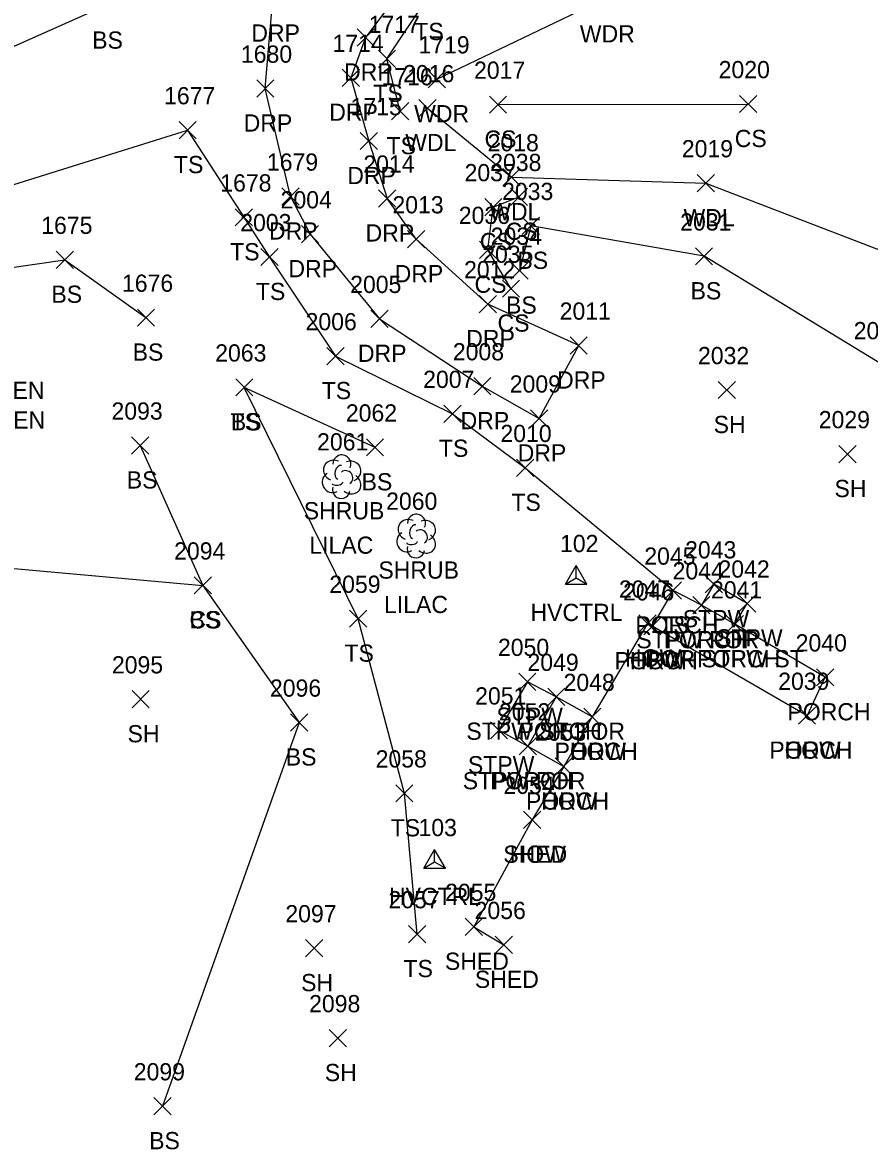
# Model space of a CAD drawing. Extents: x 1761340 to 1763889, y 696770 to 706023.
# Drawn here: x 1761761.6 to 1761860, y 700672.8 to 700803.7 of the extents above; entities that cross this region are included whole.
import ezdxf

# ---------------------------------------------------------------- set-up
doc = ezdxf.new("R2010")
doc.units = 0
for name, color, linetype in [('C_A', 7, 'Continuous'), ('C_I', 7, 'Continuous'), ('CPSM', 7, 'Continuous'), ('L_A', 7, 'Continuous'), ('L_C', 7, 'Continuous'), ('L_I', 7, 'Continuous'), ('L_TIC', 7, 'Continuous'), ('LAWA', 7, 'Continuous'), ('LBC', 7, 'Continuous'), ('LBF', 7, 'Continuous'), ('LELB', 7, 'Continuous'), ('LSH', 7, 'Continuous'), ('R_A', 7, 'Continuous'), ('R_I', 7, 'Continuous'), ('R_TIC', 7, 'Continuous'), ('RDP', 7, 'Continuous')]:
    doc.layers.add(name, color=color, linetype=linetype)

msp = doc.modelspace()

# ---------------------------------------------------------------- linework, layer by layer
at = {"layer": 'CPSM'}
for p, q in [((1761824.67, 700738.48), (1761825.92, 700740.65)), ((1761827.17, 700738.48), (1761825.92, 700740.65)), ((1761825.92, 700739.21), (1761825.92, 700740.65)), ((1761824.67, 700738.48), (1761825.92, 700739.21)), ((1761825.92, 700739.21), (1761825.92, 700739.21)), ((1761825.92, 700739.21), (1761827.17, 700738.48)), ((1761824.67, 700738.48), (1761827.17, 700738.48)), ((1761808.22, 700705.5), (1761809.47, 700707.66)), ((1761810.72, 700705.5), (1761809.47, 700707.66)), ((1761809.47, 700706.22), (1761809.47, 700707.66)), ((1761808.22, 700705.5), (1761809.47, 700706.22)), ((1761809.47, 700706.22), (1761809.47, 700706.22)), ((1761809.47, 700706.22), (1761810.72, 700705.5)), ((1761808.22, 700705.5), (1761810.72, 700705.5))]:
    msp.add_line(p, q, dxfattribs=at)
at = {"layer": 'L_TIC'}
for points in [[(1761802.94, 700798.51), (1761804.94, 700800.51)], [(1761804.94, 700798.51), (1761802.94, 700800.51)], [(1761808.72, 700796.14), (1761810.72, 700798.14)], [(1761810.72, 700796.14), (1761808.72, 700798.14)], [(1761815.83, 700793.19), (1761817.83, 700795.19)], [(1761817.83, 700793.19), (1761815.83, 700795.19)], [(1761844.9, 700793.26), (1761846.9, 700795.26)], [(1761846.9, 700793.26), (1761844.9, 700795.26)], [(1761804.48, 700792.43), (1761806.48, 700794.43)], [(1761806.48, 700792.43), (1761804.48, 700794.43)], [(1761807.64, 700792.79), (1761809.64, 700794.79)], [(1761809.64, 700792.79), (1761807.64, 700794.79)], [(1761779.78, 700790.23), (1761781.78, 700792.23)], [(1761781.78, 700790.23), (1761779.78, 700792.23)], [(1761817.4, 700784.77), (1761819.4, 700786.77)], [(1761819.4, 700784.77), (1761817.4, 700786.77)], [(1761839.97, 700784.07), (1761841.97, 700786.07)], [(1761841.97, 700784.07), (1761839.97, 700786.07)], [(1761818.27, 700782.48), (1761820.27, 700784.48)], [(1761820.27, 700782.48), (1761818.27, 700784.48)], [(1761815.29, 700781.29), (1761817.29, 700783.29)], [(1761817.29, 700781.29), (1761815.29, 700783.29)], [(1761786.31, 700780.1), (1761788.31, 700782.1)], [(1761788.31, 700780.1), (1761786.31, 700782.1)], [(1761819.65, 700779.11), (1761821.65, 700781.11)], [(1761821.65, 700779.11), (1761819.65, 700781.11)], [(1761814.67, 700776.33), (1761816.67, 700778.33)], [(1761816.67, 700776.33), (1761814.67, 700778.33)], [(1761765.51, 700775.17), (1761767.51, 700777.17)], [(1761767.51, 700775.17), (1761765.51, 700777.17)], [(1761789.3, 700775.49), (1761791.3, 700777.49)], [(1761791.3, 700775.49), (1761789.3, 700777.49)], [(1761839.77, 700775.57), (1761841.77, 700777.57)], [(1761841.77, 700775.57), (1761839.77, 700777.57)], [(1761818.33, 700773.91), (1761820.33, 700775.91)], [(1761820.33, 700773.91), (1761818.33, 700775.91)], [(1761817.34, 700771.82), (1761819.34, 700773.82)], [(1761819.34, 700771.82), (1761817.34, 700773.82)], [(1761774.94, 700768.45), (1761776.94, 700770.45)], [(1761776.94, 700768.45), (1761774.94, 700770.45)], [(1761796.95, 700763.98), (1761798.95, 700765.98)], [(1761798.95, 700763.98), (1761796.95, 700765.98)], [(1761786.36, 700760.35), (1761788.36, 700762.35)], [(1761788.36, 700760.35), (1761786.36, 700762.35)], [(1761786.36, 700760.35), (1761788.36, 700762.35)], [(1761788.36, 700760.35), (1761786.36, 700762.35)], [(1761842.41, 700760.04), (1761844.41, 700762.04)], [(1761844.41, 700760.04), (1761842.41, 700762.04)], [(1761810.56, 700757.28), (1761812.56, 700759.28)], [(1761812.56, 700757.28), (1761810.56, 700759.28)], [(1761774.27, 700753.6), (1761776.27, 700755.6)], [(1761776.27, 700753.6), (1761774.27, 700755.6)], [(1761801.55, 700753.38), (1761803.55, 700755.38)], [(1761803.55, 700753.38), (1761801.55, 700755.38)], [(1761856.44, 700752.6), (1761858.44, 700754.6)], [(1761858.44, 700752.6), (1761856.44, 700754.6)], [(1761818.98, 700751), (1761820.98, 700753)], [(1761820.98, 700751), (1761818.98, 700753)], [(1761781.55, 700737.35), (1761783.55, 700739.35)], [(1761783.55, 700737.35), (1761781.55, 700739.35)], [(1761781.55, 700737.35), (1761783.55, 700739.35)], [(1761783.55, 700737.35), (1761781.55, 700739.35)], [(1761836.17, 700736.75), (1761838.17, 700738.75)], [(1761838.17, 700736.75), (1761836.17, 700738.75)], [(1761836.17, 700736.75), (1761838.17, 700738.75)], [(1761838.17, 700736.75), (1761836.17, 700738.75)], [(1761840.91, 700737.48), (1761842.91, 700739.48)], [(1761842.91, 700737.48), (1761840.91, 700739.48)], [(1761839.46, 700735.04), (1761841.46, 700737.04)], [(1761841.46, 700735.04), (1761839.46, 700737.04)], [(1761839.46, 700735.04), (1761841.46, 700737.04)], [(1761841.46, 700735.04), (1761839.46, 700737.04)], [(1761844.79, 700735.25), (1761846.79, 700737.25)], [(1761846.79, 700735.25), (1761844.79, 700737.25)], [(1761799.59, 700733.48), (1761801.59, 700735.48)], [(1761801.59, 700733.48), (1761799.59, 700735.48)], [(1761833.21, 700732.92), (1761835.21, 700734.92)], [(1761835.21, 700732.92), (1761833.21, 700734.92)], [(1761843.35, 700732.83), (1761845.35, 700734.83)], [(1761845.35, 700732.83), (1761843.35, 700734.83)], [(1761843.35, 700732.83), (1761845.35, 700734.83)], [(1761845.35, 700732.83), (1761843.35, 700734.83)], [(1761833.76, 700732.6), (1761835.76, 700734.6)], [(1761835.76, 700732.6), (1761833.76, 700734.6)], [(1761833.76, 700732.6), (1761835.76, 700734.6)], [(1761835.76, 700732.6), (1761833.76, 700734.6)], [(1761819.25, 700726.15), (1761821.25, 700728.15)], [(1761821.25, 700726.15), (1761819.25, 700728.15)], [(1761853.84, 700726.67), (1761855.84, 700728.67)], [(1761855.84, 700726.67), (1761853.84, 700728.67)], [(1761774.32, 700724.12), (1761776.32, 700726.12)], [(1761776.32, 700724.12), (1761774.32, 700726.12)], [(1761822.61, 700724.41), (1761824.61, 700726.41)], [(1761824.61, 700724.41), (1761822.61, 700726.41)], [(1761822.61, 700724.41), (1761824.61, 700726.41)], [(1761824.61, 700724.41), (1761822.61, 700726.41)], [(1761851.74, 700722.21), (1761853.74, 700724.21)], [(1761853.74, 700722.21), (1761851.74, 700724.21)], [(1761851.74, 700722.21), (1761853.74, 700724.21)], [(1761853.74, 700722.21), (1761851.74, 700724.21)], [(1761792.74, 700721.42), (1761794.74, 700723.42)], [(1761794.74, 700721.42), (1761792.74, 700723.42)], [(1761826.79, 700722.08), (1761828.79, 700724.08)], [(1761828.79, 700722.08), (1761826.79, 700724.08)], [(1761826.79, 700722.08), (1761828.79, 700724.08)], [(1761828.79, 700722.08), (1761826.79, 700724.08)], [(1761815.95, 700720.51), (1761817.95, 700722.51)], [(1761817.95, 700720.51), (1761815.95, 700722.51)], [(1761819.29, 700718.66), (1761821.29, 700720.66)], [(1761821.29, 700718.66), (1761819.29, 700720.66)], [(1761819.29, 700718.66), (1761821.29, 700720.66)], [(1761821.29, 700718.66), (1761819.29, 700720.66)], [(1761823.47, 700716.3), (1761825.47, 700718.3)], [(1761825.47, 700716.3), (1761823.47, 700718.3)], [(1761823.47, 700716.3), (1761825.47, 700718.3)], [(1761825.47, 700716.3), (1761823.47, 700718.3)], [(1761804.96, 700713.19), (1761806.96, 700715.19)], [(1761806.96, 700713.19), (1761804.96, 700715.19)], [(1761819.81, 700710.12), (1761821.81, 700712.12)], [(1761821.81, 700710.12), (1761819.81, 700712.12)], [(1761819.81, 700710.12), (1761821.81, 700712.12)], [(1761821.81, 700710.12), (1761819.81, 700712.12)], [(1761813.03, 700697.69), (1761815.03, 700699.69)], [(1761815.03, 700697.69), (1761813.03, 700699.69)], [(1761806.45, 700696.84), (1761808.45, 700698.84)], [(1761808.45, 700696.84), (1761806.45, 700698.84)], [(1761794.47, 700695.21), (1761796.47, 700697.21)], [(1761796.47, 700695.21), (1761794.47, 700697.21)], [(1761816.51, 700695.59), (1761818.51, 700697.59)], [(1761818.51, 700695.59), (1761816.51, 700697.59)], [(1761797.23, 700684.76), (1761799.23, 700686.76)], [(1761799.23, 700684.76), (1761797.23, 700686.76)], [(1761776.87, 700676.85), (1761778.87, 700678.85)], [(1761778.87, 700676.85), (1761776.87, 700678.85)]]:
    msp.add_lwpolyline(points, dxfattribs=at)
at = {"layer": 'LAWA'}
for points in [[(1761809.72, 700797.14), (1761828.97, 700806.42), (1761852.65, 700809.17), (1761873.57, 700806.1)], [(1761808.64, 700793.79), (1761818.4, 700785.77), (1761840.97, 700785.07), (1761868.07, 700774.64), (1761881.9, 700755.26)]]:
    msp.add_lwpolyline(points, dxfattribs=at)
at = {"layer": 'LBC'}
for points in [[(1761852.74, 700723.21), (1761834.76, 700733.6), (1761834.21, 700733.92), (1761827.79, 700723.08), (1761824.47, 700717.3), (1761820.81, 700711.12)], [(1761820.81, 700711.12), (1761814.03, 700698.69), (1761817.51, 700696.59)]]:
    msp.add_lwpolyline(points, dxfattribs=at)
at = {"layer": 'LBF'}
for points in [[(1761852.74, 700723.21), (1761854.84, 700727.67), (1761844.35, 700733.83), (1761840.46, 700736.04), (1761837.17, 700737.75), (1761834.76, 700733.6)], [(1761844.35, 700733.83), (1761845.79, 700736.25), (1761841.91, 700738.48), (1761840.46, 700736.04)], [(1761823.61, 700725.41), (1761820.25, 700727.15), (1761816.95, 700721.51), (1761820.29, 700719.66)], [(1761827.79, 700723.08), (1761823.61, 700725.41), (1761820.29, 700719.66), (1761824.47, 700717.3)]]:
    msp.add_lwpolyline(points, dxfattribs=at)
at = {"layer": 'LELB'}
for points in [[(1761805.48, 700793.43), (1761803.94, 700799.51), (1761808.7, 700806.69), (1761825.93, 700814.22), (1761855.12, 700820.55), (1761878.34, 700823.71)], [(1761687.21, 700769.13), (1761700.84, 700775.67), (1761725.83, 700785.51), (1761771.25, 700805.69), (1761793.07, 700814.61), (1761809.19, 700820.93)], [(1761816.83, 700794.19), (1761845.9, 700794.26)], [(1761731.46, 700775.82), (1761780.78, 700791.23), (1761787.31, 700781.1)], [(1761818.34, 700772.82), (1761815.67, 700777.33), (1761816.29, 700782.29), (1761819.27, 700783.48)], [(1761787.31, 700781.1), (1761790.3, 700776.49)], [(1761881.9, 700755.26), (1761861.59, 700763.94), (1761840.77, 700776.57), (1761820.65, 700780.11), (1761819.33, 700774.91)], [(1761734.57, 700771.54), (1761766.51, 700776.17), (1761775.94, 700769.45)], [(1761790.3, 700776.49), (1761797.95, 700764.98), (1761811.56, 700758.28), (1761819.98, 700752), (1761837.17, 700737.75)], [(1761807.45, 700697.84), (1761805.96, 700714.19), (1761800.59, 700734.48), (1761787.36, 700761.35)], [(1761802.55, 700754.38), (1761787.36, 700761.35)], [(1761775.27, 700754.6), (1761782.55, 700738.35), (1761793.74, 700722.42), (1761777.87, 700677.85)], [(1761746.76, 700733.7), (1761758.85, 700740.46), (1761782.55, 700738.35)]]:
    msp.add_lwpolyline(points, dxfattribs=at)
at = {"layer": 'LSH'}
for p, q in [((1761798.64, 700751.02), (1761798.64, 700751.02)), ((1761798.64, 700751.02), (1761798.64, 700751.02)), ((1761807.31, 700744.13), (1761807.31, 700744.13)), ((1761807.31, 700744.13), (1761807.31, 700744.13))]:
    msp.add_line(p, q, dxfattribs=at)
for centre in [(1761798.69, 700752.45), (1761807.36, 700745.56)]:
    msp.add_arc(centre, 1.05, 335.5272, 180.9563, dxfattribs=at)
for centre, major_axis, ratio, start_param, end_param in [((1761797.85, 700751.69), (1.21, -0.51), 0.895232, 1.570796, 4.712389), ((1761798.44, 700751.48), (-0.208, -0.792), 0.645439, 3.141593, 6.283185), ((1761799.14, 700750.85), (-0.5, 0.667), 0.989748, 3.141593, 6.283185), ((1761799.68, 700751.6), (-1.14, -0.48), 0.949671, 1.570796, 4.712389), ((1761797.56, 700750.31), (0.58, -1.04), 0.959034, 3.141593, 6.283185), ((1761799.64, 700750.19), (-1.09, 0.79), 0.841452, 1.570796, 4.712389), ((1761798.64, 700749.52), (0.26, 1.06), 0.942809, 1.570796, 4.712389), ((1761798.19, 700750.27), (-0.625, -0.083), 0.423636, 0, 3.141593), ((1761806.52, 700744.8), (1.21, -0.51), 0.895232, 1.570796, 4.712389), ((1761807.1, 700744.59), (-0.208, -0.792), 0.645439, 3.141593, 6.283185), ((1761808.35, 700744.71), (-1.14, -0.48), 0.949671, 1.570796, 4.712389), ((1761806.23, 700743.42), (0.58, -1.04), 0.959034, 3.141593, 6.283185), ((1761807.81, 700743.96), (-0.5, 0.667), 0.989748, 3.141593, 6.283185), ((1761808.31, 700743.3), (-1.09, 0.79), 0.841452, 1.570796, 4.712389), ((1761807.31, 700742.63), (0.26, 1.06), 0.942809, 1.570796, 4.712389), ((1761806.85, 700743.38), (-0.625, -0.083), 0.423636, 0, 3.141593)]:
    msp.add_ellipse(centre, major_axis=major_axis, ratio=ratio, start_param=start_param, end_param=end_param, dxfattribs=at)
at = {"layer": 'R_TIC'}
for points in [[(1761800.46, 700800.99), (1761802.46, 700802.99)], [(1761802.46, 700800.99), (1761800.46, 700802.99)], [(1761798.74, 700796.31), (1761800.74, 700798.31)], [(1761800.74, 700796.31), (1761798.74, 700798.31)], [(1761788.8, 700795.06), (1761790.8, 700797.06)], [(1761790.8, 700795.06), (1761788.8, 700797.06)], [(1761800.84, 700788.96), (1761802.84, 700790.96)], [(1761802.84, 700788.96), (1761800.84, 700790.96)], [(1761791.74, 700782.52), (1761793.74, 700784.52)], [(1761793.74, 700782.52), (1761791.74, 700784.52)], [(1761802.96, 700782.29), (1761804.96, 700784.29)], [(1761804.96, 700782.29), (1761802.96, 700784.29)], [(1761794, 700778.14), (1761796, 700780.14)], [(1761796, 700778.14), (1761794, 700780.14)], [(1761806.34, 700777.56), (1761808.34, 700779.56)], [(1761808.34, 700777.56), (1761806.34, 700779.56)], [(1761814.66, 700770.02), (1761816.66, 700772.02)], [(1761816.66, 700770.02), (1761814.66, 700772.02)], [(1761802.07, 700768.31), (1761804.07, 700770.31)], [(1761804.07, 700768.31), (1761802.07, 700770.31)], [(1761825.21, 700765.21), (1761827.21, 700767.21)], [(1761827.21, 700765.21), (1761825.21, 700767.21)], [(1761814.01, 700760.49), (1761816.01, 700762.49)], [(1761816.01, 700760.49), (1761814.01, 700762.49)], [(1761820.63, 700756.74), (1761822.63, 700758.74)], [(1761822.63, 700756.74), (1761820.63, 700758.74)]]:
    msp.add_lwpolyline(points, dxfattribs=at)
at = {"layer": 'RDP'}
for points in [[(1761909.75, 700852.01), (1761910.06, 700848.6), (1761904.32, 700847.79), (1761900.72, 700845.11), (1761895.97, 700834.47), (1761888.06, 700828.96), (1761879.46, 700828.71), (1761868.22, 700828.16), (1761843.53, 700821.53), (1761821.66, 700815.81), (1761806.46, 700808.73), (1761801.46, 700801.99), (1761799.74, 700797.31), (1761801.84, 700789.96)], [(1761792.74, 700783.52), (1761789.8, 700796.06), (1761790.69, 700806.51), (1761793.91, 700812.38), (1761809.19, 700820.93), (1761834.4, 700828.2), (1761856.49, 700833.67), (1761872.42, 700837.86), (1761886.1, 700844.23), (1761888.88, 700847.64), (1761886.86, 700850.87)], [(1761801.84, 700789.96), (1761803.96, 700783.29)], [(1761792.74, 700783.52), (1761795, 700779.14)], [(1761795, 700779.14), (1761803.07, 700769.31), (1761815.01, 700761.49), (1761821.63, 700757.74), (1761826.21, 700766.21), (1761815.66, 700771.02), (1761807.34, 700778.56), (1761803.96, 700783.29)]]:
    msp.add_lwpolyline(points, dxfattribs=at)

# ---------------------------------------------------------------- texts
at = {"layer": 'C_A'}
for p in [(1761820.61, 700734.21), (1761804.17, 700701.22)]:
    msp.add_text('HVCTRL', height=2, dxfattribs=at).set_placement(p)
at = {"layer": 'C_I'}
for s, p in [('102', (1761824.04, 700742.21)), ('103', (1761807.6, 700709.22))]:
    msp.add_text(s, height=2, dxfattribs=at).set_placement(p)
at = {"layer": 'L_A'}
for s, p in [('BS', (1761769.69, 700800.69)), ('TS', (1761807.11, 700801.69)), ('WDR', (1761826.34, 700801.42)), ('TS', (1761802.35, 700794.51)), ('WDR', (1761807.09, 700792.14)), ('CS', (1761815.27, 700789.19)), ('CS', (1761844.34, 700789.26)), ('TS', (1761803.89, 700788.43)), ('WDL', (1761806.06, 700788.79)), ('TS', (1761779.19, 700786.23)), ('WDL', (1761815.82, 700780.77)), ('WDL', (1761838.39, 700780.07)), ('CS', (1761817.71, 700778.48)), ('CS', (1761814.73, 700777.29)), ('TS', (1761785.72, 700776.1)), ('BS', (1761819.09, 700775.11)), ('CS', (1761814.11, 700772.33)), ('BS', (1761764.95, 700771.17)), ('TS', (1761788.71, 700771.49)), ('BS', (1761839.21, 700771.57)), ('BS', (1761817.77, 700769.91)), ('CS', (1761816.78, 700767.82)), ('BS', (1761774.39, 700764.45)), ('GARDEN', (1761752.71, 700760.01)), ('TS', (1761796.36, 700759.98)), ('GARDEN', (1761752.79, 700756.55)), ('GARDEN', (1761752.79, 700756.55)), ('TS', (1761785.77, 700756.35)), ('BS', (1761785.8, 700756.35)), ('SH', (1761841.89, 700756.04)), ('TS', (1761809.97, 700753.28)), ('BS', (1761773.71, 700749.6)), ('BS', (1761800.99, 700749.38)), ('SH', (1761855.93, 700748.6)), ('SHRUB', (1761794.27, 700746.02)), ('TS', (1761818.39, 700747)), ('SHRUB', (1761802.94, 700739.13)), ('CS', (1761780.99, 700733.35)), ('BS', (1761780.99, 700733.35)), ('PORCH', (1761832.79, 700732.75)), ('TS', (1761835.58, 700732.75)), ('STPW', (1761838.3, 700733.48)), ('STPW POR', (1761832.91, 700731.04)), ('PORCH', (1761836.08, 700731.04)), ('STPW', (1761842.18, 700731.25)), ('TS', (1761799, 700729.48)), ('HOW', (1761831.6, 700728.92)), ('POR STPW ST', (1761833.93, 700728.83)), ('PORCH', (1761839.97, 700728.83)), ('PORCH', (1761830.38, 700728.6)), ('HOW', (1761832.15, 700728.6)), ('STPW', (1761816.65, 700722.15)), ('PORCH', (1761850.46, 700722.67)), ('SH', (1761773.8, 700720.12)), ('STPW ST POR', (1761813.16, 700720.41)), ('PORCH', (1761819.23, 700720.41)), ('BS', (1761792.18, 700717.42)), ('PORCH', (1761823.41, 700718.08)), ('HOW', (1761825.18, 700718.08)), ('PORCH', (1761848.36, 700718.21)), ('HOW', (1761850.13, 700718.21)), ('STPW', (1761813.34, 700716.51)), ('STPW POR', (1761812.74, 700714.66)), ('PORCH', (1761815.91, 700714.66)), ('PORCH', (1761820.09, 700712.3)), ('HOW', (1761821.85, 700712.3)), ('TS', (1761804.37, 700709.19)), ('SHED', (1761817.45, 700706.12)), ('HOW', (1761818.19, 700706.12)), ('SHED', (1761810.67, 700693.69)), ('TS', (1761805.86, 700692.84)), ('SH', (1761793.96, 700691.21)), ('SHED', (1761814.15, 700691.59)), ('SH', (1761796.72, 700680.76)), ('BS', (1761776.31, 700672.85))]:
    msp.add_text(s, height=2, dxfattribs=at).set_placement(p)
at = {"layer": 'L_C'}
for p in [(1761794.92, 700742.02), (1761803.59, 700735.13)]:
    msp.add_text('LILAC', height=2, dxfattribs=at).set_placement(p)
at = {"layer": 'L_I'}
for s, p in [('1717', (1761801.81, 700802.51)), ('1719', (1761807.59, 700800.14)), ('2016', (1761805.81, 700796.79)), ('2017', (1761814.05, 700797.19)), ('2020', (1761842.47, 700797.26)), ('1716', (1761803.3, 700796.43)), ('1677', (1761778.04, 700794.23)), ('2018', (1761815.63, 700788.77)), ('2019', (1761838.19, 700788.07)), ('2038', (1761815.93, 700786.48)), ('2037', (1761812.95, 700785.29)), ('1678', (1761784.57, 700784.1)), ('2033', (1761817.31, 700783.11)), ('2036', (1761812.28, 700780.33)), ('1675', (1761763.77, 700779.17)), ('2003', (1761786.89, 700779.49)), ('2031', (1761838, 700779.57)), ('2034', (1761815.99, 700777.91)), ('2035', (1761815, 700775.82)), ('1676', (1761773.15, 700772.45)), ('2006', (1761794.48, 700767.98)), ('2030', (1761858.16, 700766.94)), ('2063', (1761783.98, 700764.35)), ('2063', (1761783.98, 700764.35)), ('2032', (1761840.07, 700764.04)), ('2007', (1761808.14, 700761.28)), ('2093', (1761771.93, 700757.6)), ('2062', (1761799.16, 700757.38)), ('2029', (1761854.1, 700756.6)), ('2010', (1761817.12, 700755)), ('2061', (1761795.82, 700754.02)), ('2060', (1761803.84, 700747.13)), ('2094', (1761779.21, 700741.35)), ('2094', (1761779.21, 700741.35)), ('2045', (1761833.83, 700740.75)), ('2045', (1761833.83, 700740.75)), ('2043', (1761838.57, 700741.48)), ('2042', (1761842.45, 700739.25)), ('2044', (1761837.12, 700739.04)), ('2044', (1761837.12, 700739.04)), ('2059', (1761797.24, 700737.48)), ('2047', (1761830.88, 700736.92)), ('2046', (1761831.37, 700736.6)), ('2046', (1761831.37, 700736.6)), ('2041', (1761841.58, 700736.83)), ('2041', (1761841.58, 700736.83)), ('2050', (1761816.83, 700730.15)), ('2040', (1761851.42, 700730.67)), ('2095', (1761771.98, 700728.12)), ('2049', (1761820.26, 700728.41)), ('2049', (1761820.26, 700728.41)), ('2048', (1761824.45, 700726.08)), ('2048', (1761824.45, 700726.08)), ('2039', (1761849.39, 700726.21)), ('2039', (1761849.39, 700726.21)), ('2096', (1761790.34, 700725.42)), ('2051', (1761814.18, 700724.51)), ('2052', (1761816.95, 700722.66)), ('2052', (1761816.95, 700722.66)), ('2053', (1761821.13, 700720.3)), ('2053', (1761821.13, 700720.3)), ('2058', (1761802.62, 700717.19)), ('2054', (1761817.47, 700714.12)), ('2054', (1761817.47, 700714.12)), ('2055', (1761810.69, 700701.69)), ('2057', (1761804.11, 700700.84)), ('2097', (1761792.13, 700699.21)), ('2056', (1761814.12, 700699.59)), ('2098', (1761794.89, 700688.76)), ('2099', (1761774.52, 700680.85))]:
    msp.add_text(s, height=2, dxfattribs=at).set_placement(p)
at = {"layer": 'R_A'}
for p in [(1761788.18, 700801.51), (1761798.95, 700796.99), (1761797.23, 700792.31), (1761787.29, 700791.06), (1761799.33, 700784.96), (1761790.23, 700778.52), (1761801.45, 700778.29), (1761792.49, 700774.14), (1761804.83, 700773.56), (1761813.15, 700766.02), (1761800.56, 700764.31), (1761823.7, 700761.21), (1761812.49, 700756.49), (1761819.12, 700752.74)]:
    msp.add_text('DRP', height=2, dxfattribs=at).set_placement(p)
at = {"layer": 'R_I'}
for s, p in [('1714', (1761797.61, 700800.31)), ('1680', (1761786.97, 700799.06)), ('1715', (1761799.71, 700792.96)), ('1679', (1761789.99, 700786.52)), ('2014', (1761801.19, 700786.29)), ('2004', (1761791.58, 700782.14)), ('2013', (1761804.57, 700781.56)), ('2012', (1761812.89, 700774.02)), ('2005', (1761799.66, 700772.31)), ('2011', (1761824, 700769.21)), ('2008', (1761811.59, 700764.49)), ('2009', (1761818.2, 700760.74))]:
    msp.add_text(s, height=2, dxfattribs=at).set_placement(p)

doc.saveas('drawing.dxf')
